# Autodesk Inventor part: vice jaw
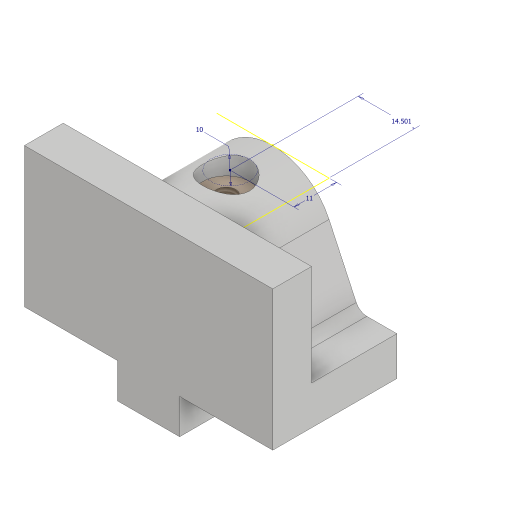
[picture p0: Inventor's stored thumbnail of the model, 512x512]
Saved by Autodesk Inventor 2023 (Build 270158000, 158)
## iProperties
Created: 2016-03
Part Number: vice jaw
Material: Generic
Document SubType Name: Modeling
Designer: Sandeep
Density: 1 g/cm^3
Appearance: Default
Mass: 55.5986 g
Surface Area: 129.526 cm^2
Volume: 55.5986 cm^3
Author: Sandeep
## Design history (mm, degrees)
sketch "Sketch1"
  geometry: L1 (0, 0)-(-32, 0); L2 (-32, 0)-(-32, 36); L3 (-32, 36)-(-22, 36); L4 (-22, 36)-(-22, 10); L5 (-22, 10)-(0, 10); L6 (0, 10)-(0, 0)
  constraints: 12 end point, 5 perpendicular, 1 horizontal
  dimensions: "d0" = 36 distance between parallel lines of L1 L3; "d1" = 32 distance of L1.start L1.end; "d2" = 10 distance of L5.end L1.start; "d3" = 10 distance of L2.end L3.end
extrude "Extrusion1" new body sketch "Sketch1" stored distance "d4" = 64; taper "d5" = 0 deg
sketch "Sketch2"
  geometry: L1 (64, 10)-(64, 0) reference; L2 (64, 10)-(64, 0); L3 (64, 0)-(54.317, 0); L4 (64, 0)-(0, 0) reference; L5 (54.317, 0)-(46.501, -16.762); L6 (0, 0)-(0, 10); L7 (0, 10)-(64, 10); L8 (64, -26)-(0, -26) reference; L9 (0, 0)-(9.683, 0); L10 (32, 10)-(32, -39.451); L11 (9.683, 0)-(17.499, -16.762); A1 r 16 centre (32, -10) between (17.499, -16.762) and (46.501, -16.762); 1 further point
  constraints: 16 end point, 3 point on line, 2 collinear, 2 perpendicular, 2 point on circle, 2 symmetric about line, 2 tangent, 1 centre point, 1 coincident, 1 vertical
  dimensions: "d8" = 16 radius of A1; "d9" = 50 deg angle of L11 L5
extrude "Extrusion2" join sketch "Sketch2" stored distance "d10" = 32; taper "d11" = 0 deg
fillet "Fillet1" dims "d12" = 3
sketch "Sketch3"
  geometry: L1 (40, 0)-(40, 9); L2 (40, 9)-(24, 9); L3 (24, 9)-(24, 0); L4 (24, 0)-(40, 0); L5 (0, 0)-(64, 0) reference; L6 (32, 0)-(32, -54.171)
  constraints: 10 end point, 2 perpendicular, 2 vertical, 1 collinear, 1 point on line, 1 other
  dimensions: "d13" = 16 distance between parallel lines of L3 L1; "d14" = 9 distance of L2.end L3.end
extrude "Extrusion3" join sketch "Sketch3" stored distance "d15" = 32; taper "d16" = 0 deg
sketch "Sketch4"
  geometry: L1 (-24, 19)-(-40, 19) reference; L2 (-32, 19)-(-32, -29.453); C1 r 6 at (-32, -10); A1 r 16 centre (-32, -10) between (-46.501, -16.762) and (-17.499, -16.762) reference; 1 further point
  constraints: 2 end point, 1 centre point, 1 concentric, 1 midpoint, 1 point on line, 1 vertical
  dimensions: "d17" = 12 diameter of C1
extrude "Extrusion4" cut sketch "Sketch4" distance "d18" = 24; taper "d19" = 0 deg
sketch "Sketch6"
  geometry: 1 further point
workplane "Work Plane1"
sketch "Sketch7"
  geometry: L1 (14.501, 0)-(-14.501, 0) reference; L2 (14.501, 0)-(14.501, -22) reference; C1 r 5 at (0, -11); 1 further point
  constraints: 1 centre point
  dimensions: "d22" = 10 diameter of C1; "d23" = 11 distance from line of L1 C1.centre; "d24" = 14.50092 distance from line of C1.centre L2
workplane "Work Plane2"
hole "Hole1" diameter "d37" = 4.917; stored, may be unused: countersink angle "d41" = 90 deg, drill point angle "d43" = 118 deg; dims "d35" = 8, "d36" = 8, "d38" = 12, "d39" = 4, "d40" = 2, "d42" = 16
hole "Hole2" diameter "d46" = 4.917; stored, may be unused: countersink angle "d50" = 90 deg, drill point angle "d52" = 118 deg; dims "d44" = 8, "d45" = 8, "d47" = 12, "d48" = 4, "d49" = 2, "d51" = 16
hole "Hole3" diameter "d55" = 4.917; stored, may be unused: countersink angle "d59" = 82 deg, drill point angle "d61" = 118 deg; dims "d53" = 20, "d54" = 32, "d56" = 12, "d57" = 12, "d58" = 5, "d60" = 17.1
sketch "Sketch10"
  geometry: 1 further point
body "Solid1"
